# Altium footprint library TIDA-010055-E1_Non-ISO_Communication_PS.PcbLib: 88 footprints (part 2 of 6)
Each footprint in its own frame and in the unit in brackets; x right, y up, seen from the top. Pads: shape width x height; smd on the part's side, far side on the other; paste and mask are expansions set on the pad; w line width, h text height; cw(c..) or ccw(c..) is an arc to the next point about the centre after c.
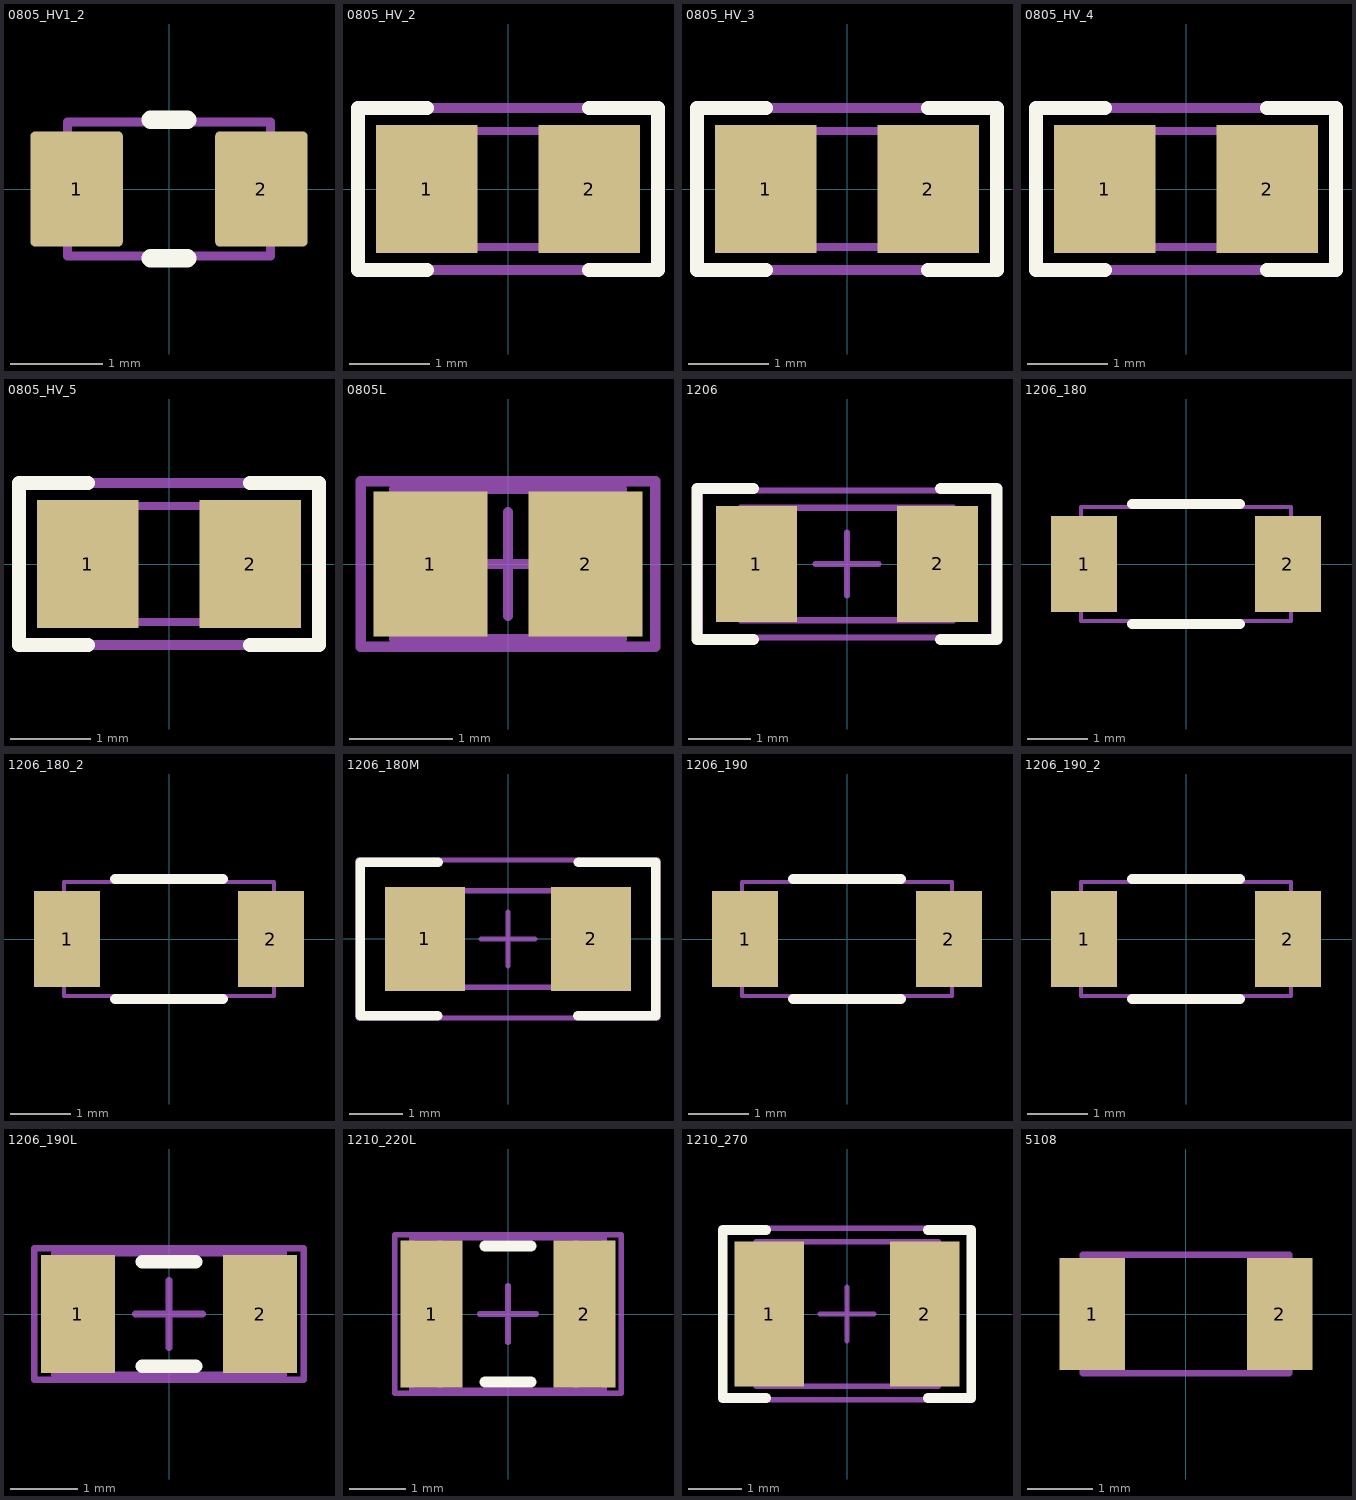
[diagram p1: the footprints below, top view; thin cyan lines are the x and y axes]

## 0805_HV1_2 [mm]
pads (2):
  rrect10% 1x1.25 smd: 1(-1,0) 2(1,0)
Top Overlay:
  lines w0.2: -0.2,-0.75 0.2,-0.75 ; -0.2,0.75 0.2,0.75
Mechanical 5:
  lines w0.1: -1.1,-0.725 1.1,-0.725 1.1,0.725 -1.1,0.725 -1.1,-0.725
  text ".Designator" at -0.863,-0.358 h0.64
3D body "0805_CapMax.stp": height 1.45, standoff 0, extent -1.1,-0.725 1.1,0.725

## 0805_HV_2 [mil]
pads (2):
  rect 50x63 smd: 1(-40,0) 2(40,0)
Top Overlay:
  lines w7: -40,-40 -74,-40 -74,0 -74,40 -40,40 ; 40,-40 74,-40 74,0 74,40 40,40
Mechanical 5:
  lines w5: -74,-40 -74,40 74,40 74,-40 -74,-40
  text ".Designator" at -34,-5 h25
Mechanical 13:
  lines w3.94: -25.59,-28.54 -25.59,28.54 ; 25.59,-28.54 25.59,28.54 ; -43.31,-28.54 -43.31,28.54 43.31,28.54 43.31,-28.54 -43.31,-28.54
3D body: height 57.09, standoff 0, extent 25.61,-28.52 43.29,28.52
3D body: height 57.09, standoff 0, extent -25.57,-28.52 25.57,28.52
3D body: height 57.09, standoff 0, extent -43.29,-28.52 -25.61,28.52

## 0805_HV_3 [mil]
pads (2):
  rect 50x63 smd: 1(-40,0) 2(40,0)
Top Overlay:
  lines w7: -40,-40 -74,-40 -74,0 -74,40 -40,40 ; 40,-40 74,-40 74,0 74,40 40,40
Mechanical 5:
  lines w5: -74,-40 -74,40 74,40 74,-40 -74,-40
  text ".Designator" at -27,-17.4 h25
Mechanical 13:
  lines w3.94: -25.59,-28.54 -25.59,28.54 ; 25.59,-28.54 25.59,28.54 ; -43.31,-28.54 -43.31,28.54 43.31,28.54 43.31,-28.54 -43.31,-28.54
3D body: height 57.09, standoff 0, extent 25.61,-28.52 43.29,28.52
3D body: height 57.09, standoff 0, extent -25.57,-28.52 25.57,28.52
3D body: height 57.09, standoff 0, extent -43.29,-28.52 -25.61,28.52

## 0805_HV_4 [mil]
pads (2):
  rect 50x63 smd: 1(-40,0) 2(40,0)
Top Overlay:
  lines w7: -40,-40 -74,-40 -74,0 -74,40 -40,40 ; 40,-40 74,-40 74,0 74,40 40,40
Mechanical 5:
  lines w5: -74,-40 74,-40 74,40 -74,40 -74,-40
  text ".Designator" at 32.43,7.63 h25
Mechanical 13:
  lines w3.94: -25.59,-28.54 -25.59,28.54 ; 25.59,-28.54 25.59,28.54 ; -43.31,-28.54 43.31,-28.54 43.31,28.54 -43.31,28.54 -43.31,-28.54
3D body: height 57.09, standoff 0, extent -43.29,-28.52 -25.61,28.52
3D body: height 57.09, standoff 0, extent -25.57,-28.52 25.57,28.52
3D body: height 57.09, standoff 0, extent 25.61,-28.52 43.29,28.52

## 0805_HV_5 [mil]
pads (2):
  rect 50x63 smd: 1(-40,0) 2(40,0)
Top Overlay:
  lines w7: -40,-40 -74,-40 -74,0 -74,40 -40,40 ; 40,-40 74,-40 74,0 74,40 40,40
Mechanical 5:
  lines w5: -74,-40 74,-40 74,40 -74,40 -74,-40
  text ".Designator" at 20,8.15 h25
Mechanical 13:
  lines w3.94: -25.59,-28.54 -25.59,28.54 ; 25.59,-28.54 25.59,28.54 ; -43.31,-28.54 43.31,-28.54 43.31,28.54 -43.31,28.54 -43.31,-28.54
3D body: height 57.09, standoff 0, extent -43.29,-28.52 -25.61,28.52
3D body: height 57.09, standoff 0, extent -25.57,-28.52 25.57,28.52
3D body: height 57.09, standoff 0, extent 25.61,-28.52 43.29,28.52

## 0805L [mm] "0805 from SM-752 data"
height 1.45
pads (2):
  rect 1.1x1.4 smd: 1(-0.75,0) 2(0.75,0)
Mechanical 5:
  lines w0.1: -1.425,-0.8 -1.425,0.8 1.425,0.8 1.425,-0.8 -1.425,-0.8
  text ".Designator" at -1.2,-0.325 h0.64
Mechanical 13:
  lines w0.1: -0.65,-0.725 -0.65,0.725 ; 0.65,-0.725 0.65,0.725 ; -1.1,-0.725 1.1,-0.725 1.1,0.725 -1.1,0.725 -1.1,-0.725
Mechanical 15:
  lines w0.1: -0.5,0 0.5,0 ; 0,-0.5 0,0.5 ; -1.425,-0.8 1.425,-0.8 1.425,0.8 -1.425,0.8 -1.425,-0.8
3D body: height 1.45, standoff 0, extent -1.099,-0.724 -0.651,0.724
3D body: height 1.45, standoff 0, extent -0.649,-0.724 0.649,0.724
3D body: height 1.45, standoff 0, extent 0.651,-0.724 1.099,0.724

## 1206 [mm] "1206 from SM-752 data"
height 1.35
pads (2):
  rect 1.3x1.85 smd: 1(-1.45,0) 2(1.45,0)
Top Overlay:
  lines w0.178: -1.5,-1.21 -2.4,-1.21 -2.4,1.21 -1.5,1.21 ; 1.5,-1.21 2.4,-1.21 2.4,1.21 1.5,1.21
Mechanical 5:
  lines w0.1: -1.7,-0.9 1.7,-0.9 1.7,0.9 -1.7,0.9 -1.7,-0.9
  text ".Designator" at -0.837,-0.264 h0.64
Mechanical 13:
  lines w0.1: -1.2,-0.9 -1.2,0.9 ; 1.2,-0.9 1.2,0.9 ; -1.7,-0.9 1.7,-0.9 1.7,0.9 -1.7,0.9 -1.7,-0.9
Mechanical 15:
  lines w0.1: -0.5,0 0.5,0 ; 0,-0.5 0,0.5 ; -2.35,-1.175 2.35,-1.175 2.35,1.175 -2.35,1.175 -2.35,-1.175
3D body: height 1.35, standoff 0, extent -1.699,-0.899 -1.201,0.899
3D body: height 1.35, standoff 0, extent -1.199,-0.899 1.199,0.899
3D body: height 1.35, standoff 0, extent 1.201,-0.899 1.699,0.899

## 1206_180 [mm] "1206_180"
height 1.8
pads (2):
  rect 1.1x1.6 smd: 1(-1.7,0) 2(1.7,0)
Top Overlay:
  lines w0.17: -0.9,-1 0.9,-1 ; -0.9,1 0.9,1
Mechanical 5:
  lines w0.07: -1.75,-0.95 1.75,-0.95 1.75,0.95 -1.75,0.95 -1.75,-0.95
  text ".Designator" at -0.838,-0.29 h0.64
3D body: height 1.8, standoff 0, extent -1.749,-0.949 -1.301,0.949
3D body: height 1.8, standoff 0, extent -1.299,-0.949 1.299,0.949
3D body: height 1.8, standoff 0, extent 1.301,-0.949 1.749,0.949

## 1206_180_2 [mm]
pads (2):
  rect 1.1x1.6 smd: 1(-1.7,0) 2(1.7,0)
Top Overlay:
  lines w0.17: -0.9,-1 0.9,-1 ; -0.9,1 0.9,1
Mechanical 5:
  lines w0.07: -1.75,-0.95 -1.75,0.95 1.75,0.95 1.75,-0.95 -1.75,-0.95
  text ".Designator" at -0.917,-0.208 h0.64
3D body: height 1.8, standoff 0, extent 1.301,-0.949 1.749,0.949
3D body: height 1.8, standoff 0, extent -1.299,-0.949 1.299,0.949
3D body: height 1.8, standoff 0, extent -1.749,-0.949 -1.301,0.949

## 1206_180M [mm] "1206_180"
height 1.8
pads (2):
  rect 1.5x1.95 smd: 1(-1.55,0) 2(1.55,0)
Top Overlay:
  lines w0.178: -2.758,-1.43 -2.753,-1.435 ; -1.313,-1.435 -2.758,-1.435 -2.758,1.435 -1.303,1.435 ; 1.306,-1.435 2.761,-1.435 2.761,1.435 1.316,1.435 ; 2.756,1.435 2.761,1.43
Mechanical 5:
  lines w0.1: -1.7,-0.9 1.7,-0.9 1.7,0.9 -1.7,0.9 -1.7,-0.9
  text ".Designator" at -0.913,-0.463 h0.64
Mechanical 15:
  lines w0.1: -0.5,0 0.5,0 ; 0,-0.5 0,0.5 ; -2.8,-1.475 -2.8,1.475 2.8,1.475 2.8,-1.475 -2.8,-1.475
3D body: height 1.8, standoff 0, extent 1.301,-0.949 1.75,0.95
3D body: height 1.8, standoff 0, extent -1.299,-0.949 1.3,0.95
3D body: height 1.8, standoff 0, extent -1.749,-0.949 -1.3,0.95

## 1206_190 [mm] "1206_190"
height 1.9
pads (2):
  rect 1.1x1.6 smd: 1(-1.7,0) 2(1.7,0)
Top Overlay:
  lines w0.17: -0.9,-1 0.9,-1 ; -0.9,1 0.9,1
Mechanical 5:
  lines w0.07: -1.75,-0.95 1.75,-0.95 1.75,0.95 -1.75,0.95 -1.75,-0.95
  text ".Designator" at -0.762,-0.417 h0.64
3D body: height 1.9, standoff 0, extent -1.749,-0.949 -1.301,0.949
3D body: height 1.9, standoff 0, extent -1.299,-0.949 1.299,0.949
3D body: height 1.9, standoff 0, extent 1.301,-0.949 1.749,0.949

## 1206_190_2 [mm]
pads (2):
  rect 1.1x1.6 smd: 1(-1.7,0) 2(1.7,0)
Top Overlay:
  lines w0.17: -0.9,-1 0.9,-1 ; -0.9,1 0.9,1
Mechanical 5:
  lines w0.07: -1.75,-0.95 -1.75,0.95 1.75,0.95 1.75,-0.95 -1.75,-0.95
  text ".Designator" at -0.531,-0.279 h0.64
3D body: height 1.9, standoff 0, extent 1.301,-0.949 1.749,0.949
3D body: height 1.9, standoff 0, extent -1.299,-0.949 1.299,0.949
3D body: height 1.9, standoff 0, extent -1.749,-0.949 -1.301,0.949

## 1206_190L [mm] "1206_190"
height 1.9
pads (2):
  rect 1.1x1.75 smd: 1(-1.35,0) 2(1.35,0)
Top Overlay:
  lines w0.2: -0.4,-0.775 0.4,-0.775 ; -0.4,0.775 0.4,0.775
Mechanical 5:
  lines w0.1: -1.7,-0.9 1.7,-0.9 1.7,0.9 -1.7,0.9 -1.7,-0.9
  text ".Designator" at -1.475,-0.4 h0.64
Mechanical 15:
  lines w0.1: -0.5,0 0.5,0 ; 0,-0.5 0,0.5 ; -2,-0.975 2,-0.975 2,0.975 -2,0.975 -2,-0.975
3D body: height 1.9, standoff 0, extent -1.749,-0.949 -1.3,0.95
3D body: height 1.9, standoff 0, extent -1.299,-0.949 1.3,0.95
3D body: height 1.9, standoff 0, extent 1.301,-0.949 1.75,0.95

## 1210_220L [mm] "1210"
height 2.2
pads (2):
  rect 1.1x2.6 smd: 1(-1.35,0) 2(1.35,0)
Top Overlay:
  lines w0.2: -0.4,-1.2 0.4,-1.2 ; -0.4,1.2 0.4,1.2
Mechanical 5:
  lines w0.1: -1.7,-1.35 -1.7,1.35 1.7,1.35 1.7,-1.35 -1.7,-1.35
  text ".Designator" at 0.919,0.175 h0.64
Mechanical 13:
  lines w0.1: -1.2,-1.35 -1.2,1.35 ; 1.2,-1.35 1.2,1.35 ; -1.7,-1.35 -1.7,1.35 1.7,1.35 1.7,-1.35 -1.7,-1.35
Mechanical 15:
  lines w0.1: -0.5,0 0.5,0 ; 0,-0.5 0,0.5 ; -2,-1.4 2,-1.4 2,1.4 -2,1.4 -2,-1.4
3D body: height 2.2, standoff 0, extent -1.699,-1.349 -1.201,1.349
3D body: height 2.2, standoff 0, extent -1.199,-1.349 1.199,1.349
3D body: height 2.2, standoff 0, extent 1.201,-1.349 1.699,1.349

## 1210_270 [mm] "1210"
height 2.7
pads (2):
  rect 1.3x2.7 smd: 1(-1.45,0) 2(1.45,0)
Top Overlay:
  lines w0.178: -1.511,-1.568 -2.316,-1.568 -2.316,1.568 -1.511,1.568 ; 1.511,-1.568 2.316,-1.568 2.316,1.568 1.511,1.568
Mechanical 5:
  lines w0.1: -1.7,-1.35 -1.7,1.35 1.7,1.35 1.7,-1.35 -1.7,-1.35
  text ".Designator" at 0.594,0.127 h0.64
Mechanical 13:
  lines w0.1: -1.2,-1.35 -1.2,1.35 ; 1.2,-1.35 1.2,1.35 ; -1.7,-1.35 1.7,-1.35 1.7,1.35 -1.7,1.35 -1.7,-1.35
Mechanical 15:
  lines w0.1: -0.5,0 0.5,0 ; 0,-0.5 0,0.5 ; -2.35,-1.6 2.35,-1.6 2.35,1.6 -2.35,1.6 -2.35,-1.6
3D body: height 2.7, standoff 0, extent 1.201,-1.349 1.699,1.349
3D body: height 2.7, standoff 0, extent -1.199,-1.349 1.199,1.349
3D body: height 2.7, standoff 0, extent -1.699,-1.349 -1.201,1.349

## 5108 [mm] "Keystone"
height 0.84
pads (2):
  rect 1.01x1.73 smd: 1(-1.445,0) 2(1.445,0)
Mechanical 5:
  lines w0.1: -1.59,-0.915 1.59,-0.915 1.59,0.915 -1.59,0.915 -1.59,-0.915
  text ".Designator" at -1.175,-0.25 h0.64
3D body "5108.stp": height 0.71, standoff 0, extent -1.524,-0.85 1.524,0.852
